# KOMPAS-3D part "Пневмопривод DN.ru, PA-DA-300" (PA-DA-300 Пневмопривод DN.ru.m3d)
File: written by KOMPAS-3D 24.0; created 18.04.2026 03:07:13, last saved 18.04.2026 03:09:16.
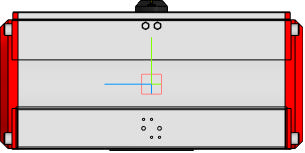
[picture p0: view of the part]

Document properties: Автор: DN.ru; Полное имя файла: C:\Работа\PA-DA-х Пневмопривод DN.ru\300\PA-DA-300 Пневмопривод DN.ru.m3d

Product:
- Part/product: Пневмопривод DN.ru  | designation PA-DA-300
    Масса: 110
    Раздел спецификации: Прочие изделия
    Примечание: D290-00302

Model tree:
1. Операция без истории:1

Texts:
  PA-DA-300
